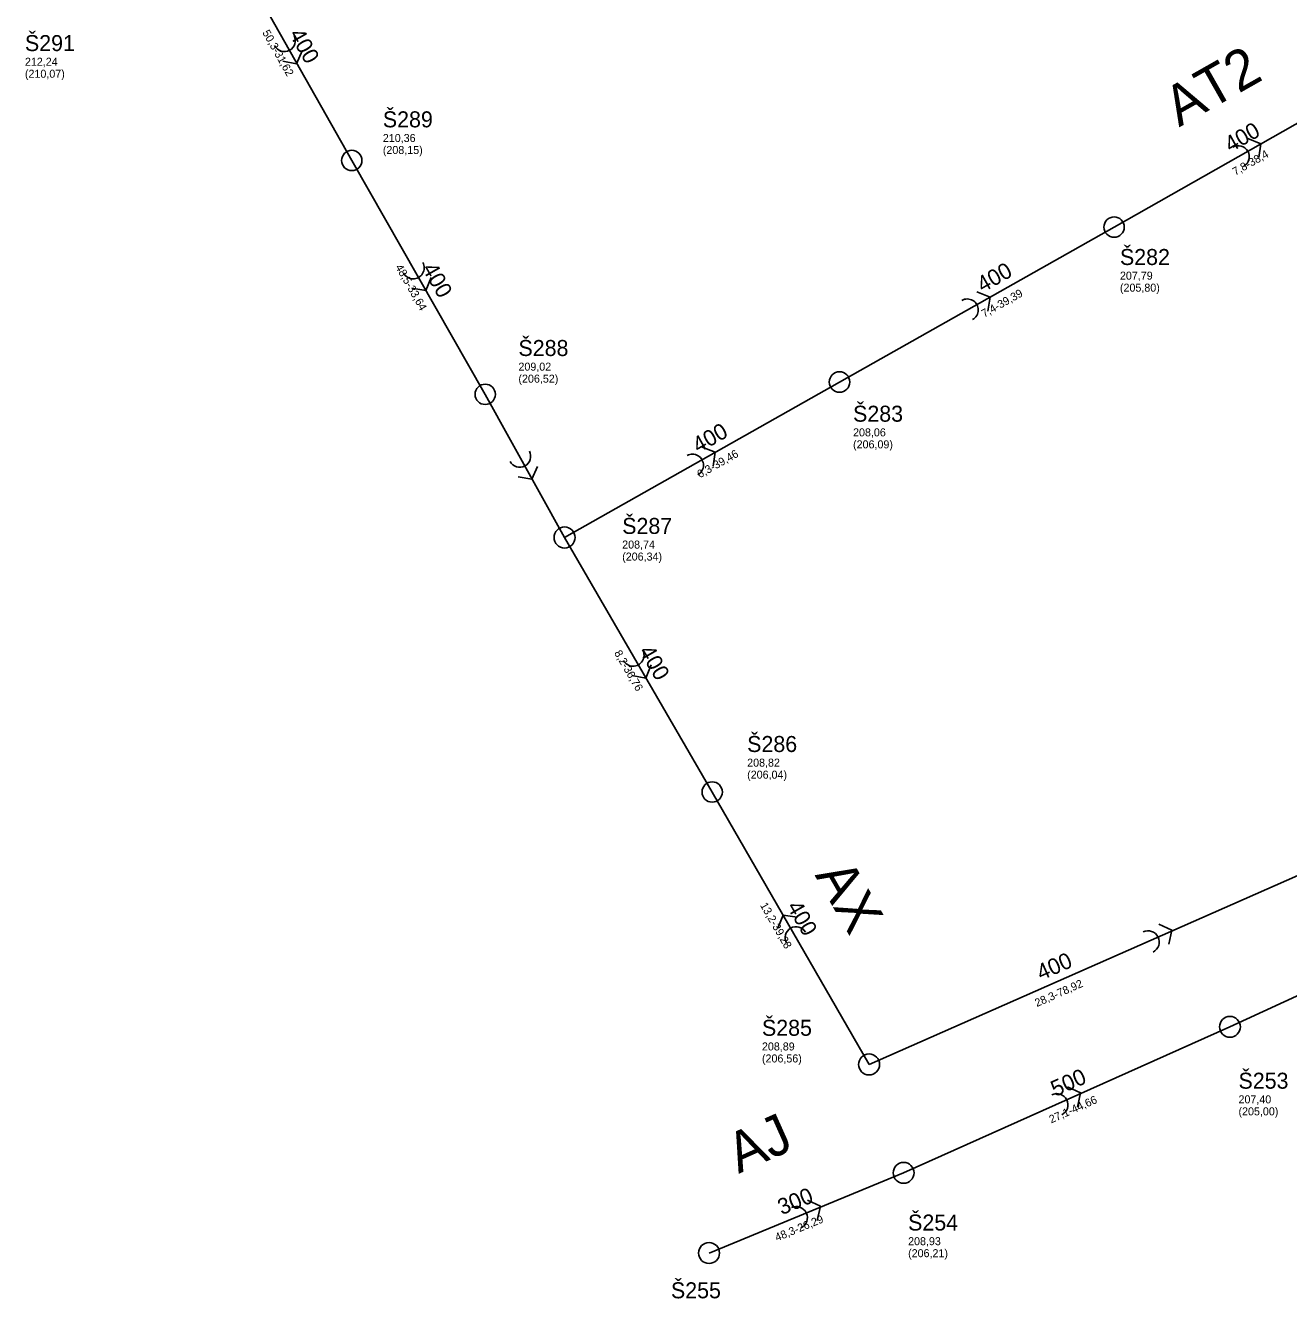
# Model space of a CAD drawing. Extents: x -574467 to -573663, y -1191209 to -1190406.
# Drawn here: x -574130.8 to -573973, y -1190808.2 to -1190649.1 of the extents above; entities that cross this region are included whole.
import ezdxf

# ---------------------------------------------------------------- set-up
doc = ezdxf.new("R2010")
doc.units = 0
for name, color, linetype in [('Vrstva 1', 7, 'Continuous'), ('Vrstva 15', 7, 'Continuous'), ('Vrstva 29', 7, 'Continuous'), ('Vrstva 35', 7, 'Continuous'), ('Vrstva 41', 7, 'Continuous'), ('Vrstva 44', 7, 'Continuous'), ('Vrstva 45', 7, 'Continuous'), ('Vrstva 56', 7, 'Continuous'), ('Vrstva 57', 7, 'Continuous')]:
    doc.layers.add(name, color=color, linetype=linetype)

# ---------------------------------------------------------------- blocks, each defined once
blk = doc.blocks.new('100')
at = {"layer": 'Vrstva 1'}
blk.add_circle((0, 0), 1.27, dxfattribs=at)
blk = doc.blocks.new('86')
at = {"layer": 'Vrstva 1'}
blk.add_lwpolyline([(0.79, 1.37), (1.89, 0), (0.79, -1.38)], dxfattribs=at)
blk.add_arc((-1.37, 0), 1.37, 270, 90, dxfattribs=at)
blk = doc.blocks.new('91')
at = {"layer": 'Vrstva 1'}
blk.add_lwpolyline([(0.79, 1.37), (1.89, 0), (0.79, -1.38)], dxfattribs=at)
blk.add_arc((-1.37, 0), 1.37, 270, 90, dxfattribs=at)

msp = doc.modelspace()

# ---------------------------------------------------------------- linework, layer by layer
at = {"layer": 'Vrstva 15'}
for p, q in [((-574105.61, -1190638.49), (-574090.06, -1190666.02)), ((-573994.83, -1190674.34), (-573961.43, -1190655.39)), ((-574090.06, -1190666.02), (-574073.39, -1190695.24)), ((-574029.13, -1190693.7), (-573994.83, -1190674.34)), ((-574063.48, -1190713.13), (-574029.13, -1190693.7)), ((-574073.39, -1190695.24), (-574063.48, -1190713.13)), ((-574063.48, -1190713.13), (-574045.04, -1190744.93)), ((-574025.44, -1190778.97), (-574045.04, -1190744.93)), ((-574025.44, -1190778.97), (-573953.23, -1190747.128)), ((-573980.36, -1190774.27), (-573947.076, -1190758.931)), ((-574021.124, -1190792.513), (-573980.36, -1190774.27)), ((-574045.43, -1190802.53), (-574021.124, -1190792.513))]:
    msp.add_line(p, q, dxfattribs=at)

# ---------------------------------------------------------------- block references
at = {"layer": 'Vrstva 29'}
for p, xscale, yscale, rotation in [((-574090.06, -1190666.02), 0.9999999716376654, 0.9999999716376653, 119.99999896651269), ((-573994.83, -1190674.34), 1.0037041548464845, 1.0037041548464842, -150.62079141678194), ((-574029.13, -1190693.7), 1.0072562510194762, 1.0072562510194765, -151.23333635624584), ((-574073.39, -1190695.24), 0.999999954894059, 0.9999999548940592, 119.00000058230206), ((-574063.48, -1190713.13), 1.0365458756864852, 1.0365458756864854, 158.02850914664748), ((-574045.04, -1190744.93), 0.9999999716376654, 0.9999999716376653, 119.99999896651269), ((-573980.36, -1190774.27), 1.022584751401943, 1.022584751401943, -154.18102569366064), ((-574025.44, -1190778.97), 1.0335064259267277, 1.033506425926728, 156.95871849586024), ((-574021.124, -1190792.513), 1.025136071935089, 1.0251360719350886, -154.74924162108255), ((-574045.43, -1190802.53), 1.0275072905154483, 1.027507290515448, -155.31089431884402)]:
    msp.add_blockref('100', p, dxfattribs=dict(at, xscale=xscale, yscale=yscale, rotation=rotation))
at = {"layer": 'Vrstva 41'}
for name, p, xscale, yscale, rotation in [('86', (-574097.835, -1190652.255), 0.9999999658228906, 0.9999999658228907, -62.00000017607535), ('86', (-573978.13, -1190664.865), 0.9999999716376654, 0.9999999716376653, 29.999998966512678), ('86', (-574081.725, -1190680.63), 0.999999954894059, 0.9999999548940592, -60.999999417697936), ('86', (-574011.98, -1190684.02), 1.0037041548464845, 1.0037041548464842, 29.379208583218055), ('86', (-574068.435, -1190704.185), 0.9999999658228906, 0.9999999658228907, -62.00000017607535), ('86', (-574046.305, -1190703.415), 1.0037041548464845, 1.0037041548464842, 29.379208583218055), ('86', (-574054.26, -1190729.03), 0.999999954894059, 0.9999999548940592, -60.999999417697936), ('86', (-574035.24, -1190761.95), 0.9999999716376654, 0.9999999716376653, 119.99999896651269), ('86', (-573989.335, -1190763.049), 1.0198568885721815, 1.0198568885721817, 26.39398240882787), ('91', (-574000.742, -1190783.392), 1.0198568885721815, 1.0198568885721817, 26.39398240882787), ('91', (-574033.277, -1190797.522), 1.025136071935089, 1.0251360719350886, 25.250758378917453)]:
    msp.add_blockref(name, p, dxfattribs=dict(at, xscale=xscale, yscale=yscale, rotation=rotation))

# ---------------------------------------------------------------- texts
at = {"layer": 'Vrstva 35'}
for s, rotation, p in [('AT2', 29.57, (-573986.707, -1190661.893)), ('AX', 299.93, (-574032.261, -1190755.314)), ('AJ', 24.11, (-574041.743, -1190792.651))]:
    msp.add_text(s, height=5, rotation=rotation, dxfattribs=at).set_placement(p)
at = {"layer": 'Vrstva 44'}
for s, rotation, p in [('400', 299.46, (-574097.938, -1190650.229)), ('400', 29.57, (-573980.298, -1190665.063)), ('400', 29.44, (-574011.253, -1190682.569)), ('400', 299.7, (-574081.331, -1190679.508)), ('400', 29.49, (-574046.774, -1190702.638)), ('400', 300.11, (-574054.214, -1190727.32)), ('400', 299.93, (-574035.763, -1190759.241)), ('400', 23.8, (-574003.954, -1190768.51)), ('500', 24.11, (-574002.182, -1190783.048)), ('300', 22.4, (-574036.355, -1190797.819))]:
    msp.add_text(s, height=2, rotation=rotation, dxfattribs=at).set_placement(p)
at = {"layer": 'Vrstva 45'}
for s, rotation, p in [('50,3-31,62', 299.46, (-574101.267, -1190650.039)), ('7,8-38,4', 29.57, (-573979.691, -1190667.939)), ('48,5-33,64', 299.7, (-574084.652, -1190679.337)), ('7,4-39,39', 29.44, (-574011.053, -1190685.676)), ('6,3-39,46', 29.49, (-574046.571, -1190705.746)), ('8,2-36,76', 300.11, (-574057.315, -1190727.555)), ('13,2-39,28', 299.93, (-574039.088, -1190759.079)), ('28,3-78,92', 23.8, (-574004.476, -1190771.8)), ('27,1-44,66', 24.11, (-574002.682, -1190786.344)), ('48,3-26,29', 22.4, (-574036.95, -1190801.094))]:
    msp.add_text(s, height=1, rotation=rotation, dxfattribs=at).set_placement(p)
at = {"layer": 'Vrstva 56'}
for s, p in [('212,24 ', (-574130.89, -1190654.18)), ('(210,07)', (-574130.89, -1190655.68)), ('210,36 ', (-574086.18, -1190663.71)), ('(208,15)', (-574086.18, -1190665.21)), ('207,79 ', (-573994.1, -1190680.91)), ('(205,80)', (-573994.1, -1190682.41)), ('209,02 ', (-574069.24, -1190692.28)), ('(206,52)', (-574069.24, -1190693.78)), ('208,06 ', (-574027.44, -1190700.49)), ('(206,09)', (-574027.44, -1190701.99)), ('208,74 ', (-574056.28, -1190714.51)), ('(206,34)', (-574056.28, -1190716.01)), ('208,82 ', (-574040.67, -1190741.76)), ('(206,04)', (-574040.67, -1190743.26)), ('208,89 ', (-574038.82, -1190777.22)), ('(206,56)', (-574038.82, -1190778.72)), ('207,40 ', (-573979.29, -1190783.83)), ('(205,00)', (-573979.29, -1190785.33)), ('208,93 ', (-574020.564, -1190801.553)), ('(206,21)', (-574020.564, -1190803.053))]:
    msp.add_text(s, height=1, dxfattribs=at).set_placement(p)
at = {"layer": 'Vrstva 57'}
for s, p in [('Š291', (-574130.89, -1190652.35)), ('Š289', (-574086.18, -1190661.88)), ('Š282', (-573994.1, -1190679.08)), ('Š288', (-574069.24, -1190690.45)), ('Š283', (-574027.44, -1190698.66)), ('Š287', (-574056.28, -1190712.68)), ('Š286', (-574040.67, -1190739.93)), ('Š285', (-574038.82, -1190775.39)), ('Š253', (-573979.29, -1190782)), ('Š254', (-574020.564, -1190799.723)), ('Š255', (-574050.19, -1190808.19))]:
    msp.add_text(s, height=2, dxfattribs=at).set_placement(p)

doc.saveas('drawing.dxf')
